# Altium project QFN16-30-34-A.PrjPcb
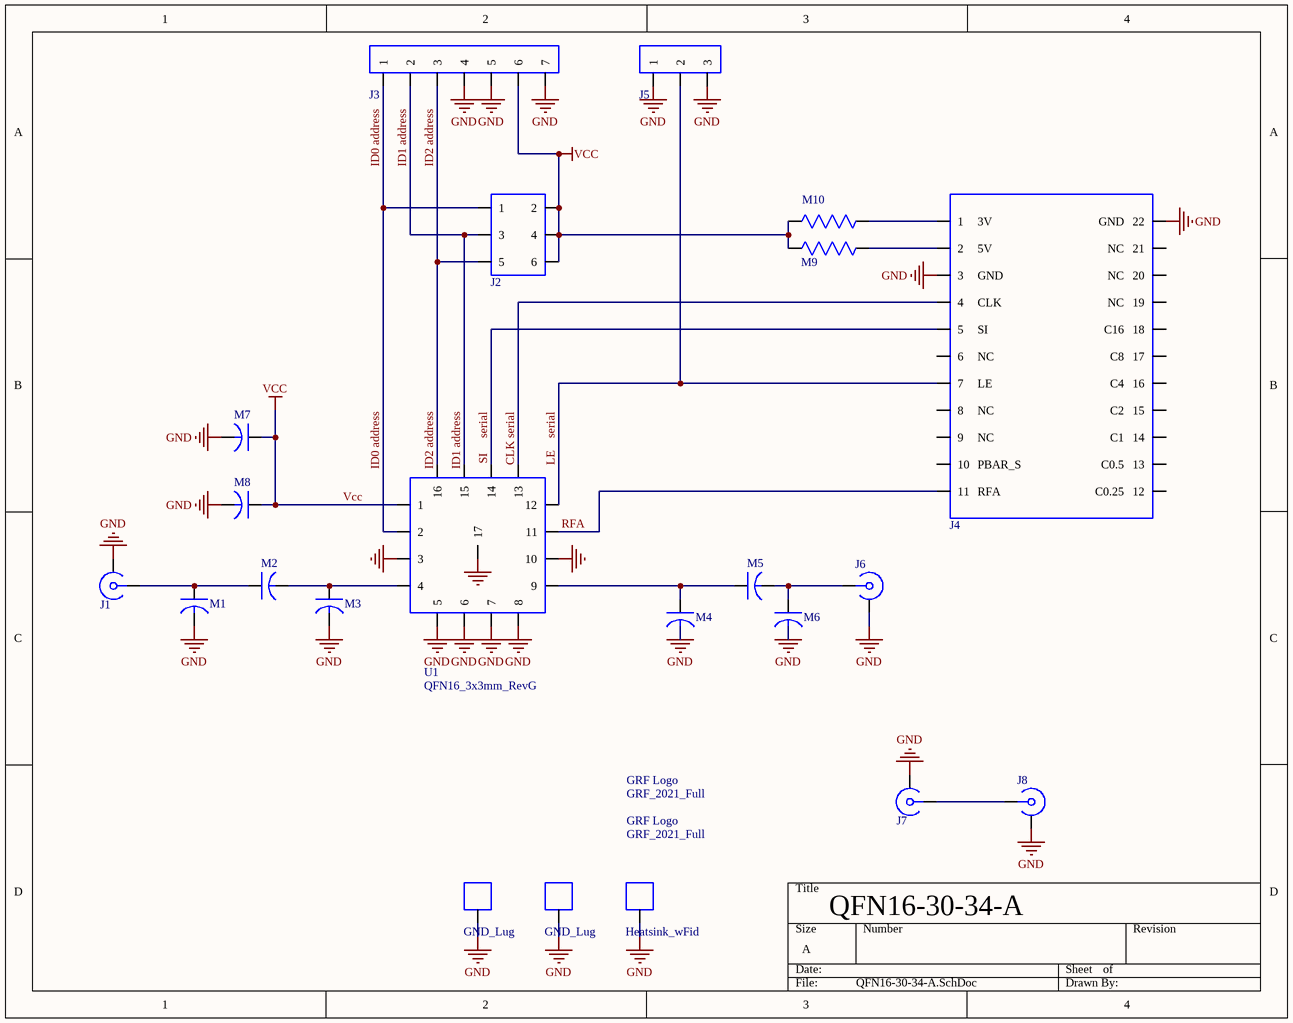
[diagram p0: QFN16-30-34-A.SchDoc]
Description: Layout updates; Modified From: DFN6-15-34-A (Eagle)
1 sheet, 24 parts. Net scope: global (net labels, ports and power ports of the same name join across sheets).
Board file: QFN16-30-34-A.PcbDoc

## Sheet QFN16-30-34-A.SchDoc
size A

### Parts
H1  Heatsink_wFid  [Heatsink_wFid]
H2  GND_Lug  [GND_Lug]
H3  GND_Lug  [GND_Lug]
J1  SMA Round_Pin_RevD + HiFreq  [SMA Round_Pin_RevD + HiFreq]  (value not drawn)
J2  Header_V_Dual-3-Pin_100MIL  [Header_V_Dual-3-Pin_100MIL]  (value not drawn)
J3  Header_H_7-Pin_100mil  [Header_H_7-Pin_100mil]  (value not drawn)
J4  USB_Interface  [USB_Interface]  (value not drawn)
J5  Header_V_3-Pin_100MIL  [Header_V_3-Pin_100MIL]  (value not drawn)
J6  SMA Round_Pin_RevD + HiFreq  [SMA Round_Pin_RevD + HiFreq]  (value not drawn)
J7  SMA Round_Pin_RevD + HiFreq  [SMA Round_Pin_RevD + HiFreq]  (value not drawn)
J8  SMA Round_Pin_RevD + HiFreq  [SMA Round_Pin_RevD + HiFreq]  (value not drawn)
Logo1  GRF_2021_Full  [GRF_2021_Full]
Logo2  GRF_2021_Full  [GRF_2021_Full]
M1  0402_20x26x22  [0402_20x26x22]  (value not drawn)
M2  0402_20x30x18  [0402_20x30x18]  (value not drawn)
M3  0402_20x26x22  [0402_20x26x22]  (value not drawn)
M4  0402_20x26x22  [0402_20x26x22]  (value not drawn)
M5  0402_20x30x18  [0402_20x30x18]  (value not drawn)
M6  0402_20x26x22  [0402_20x26x22]  (value not drawn)
M7  0402_20x26x16  [0402_20x26x16]  (value not drawn)
M8  0402_20x26x16  [0402_20x26x16]  (value not drawn)
M9  0402_23p5x27p5x15p5  [0402_20x30x18]  (value not drawn)
M10  0402_23p5x27p5x15p5  [0402_20x30x18]  (value not drawn)
U1  QFN16_3x3mm_RevG  [QFN16_3x3mm_RevG]

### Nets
GND: H1.1 H2.1 H3.1 J1.2 J3.4 J3.5 J3.7 J4.3 J4.22 J5.1 J5.3 J6.2 J7.2 J8.2 M1.1 M3.1 M4.1 M6.1 M7.1 M8.1 U1.3 U1.5 U1.6 U1.7 U1.8 U1.10 U1.17
Vcc: J2.2 J2.4 J2.6 J3.6 M7.2 M8.2 M9.1 M10.1 U1.1
CLK serial: J4.4 U1.13
ID0 address: J2.1 J3.1 U1.2
ID1 address: J2.3 J3.2 U1.15
ID2 address: J2.5 J3.3 U1.16
LE    serial: J4.7 J5.2 U1.12
RFA: J4.11 U1.11
SI     serial: J4.5 U1.14
NetJ1_1: J1.1 M1.2 M2.2
NetJ4_1: J4.1 M10.2
NetJ4_2: J4.2 M9.2
NetJ6_1: J6.1 M5.1 M6.2
NetJ7_1: J7.1 J8.1
NetM2_1: M2.1 M3.2 U1.4
NetM4_2: M4.2 M5.2 U1.9

Not connected (* = marked no-connect by the designer): J4 6 8 9 10 12 13 14 15 16 17 18 19 20 21

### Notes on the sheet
- QFN16-30-34-A

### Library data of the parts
H1-H3 = Mounting Holes
J1 J6-J8 = RF_Conn
J2 = Header_Dual-3-Pin: Header 6-Pin
J3 = Header_7-Pin: Header 7-Pin
J4 = USB_Interface: FT232H USB Interface
J5 = Header_3-Pin: Header 3-Pin
Logo1 Logo2 = GRF_Logo
M1-M8 = Capacitor
M9 M10 = Resistor
U1 = QFN16_3x3mm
